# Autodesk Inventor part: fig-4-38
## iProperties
Created: 2004-05
Part Number: fig-4-38
Document SubType Name: Modeling
Designer: CADCIM Technologies
Manufacturer: Standard
Standards Organization: Custom
Author: CADCIM Technologies
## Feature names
1. Extrusion1
2. Shell1
3. Extrusion2
4. Extrusion7
